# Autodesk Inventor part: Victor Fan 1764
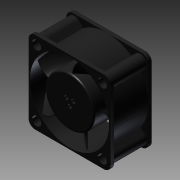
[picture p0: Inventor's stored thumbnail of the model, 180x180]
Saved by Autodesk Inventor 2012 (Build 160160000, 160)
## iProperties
Shininess: 64.0
Length Units: 11272
Angle Units: 11279
Time Units: 11290
Mass Units: 11286
Length Display Precision: 3
Angle Display Precision: 2
Compacted: True
Part Number: Victor Fan 1764
Document SubType Name: Modeling
Created: 2005-12
Designer: Owner
Material: ABS Plastic
Density: 1 g/cm^3
Density: 0.0
Volumn: 0.0
Area: 0.0
PropertySet Name: Model Information
Control State: 0
Master: False
Checked Out: False
Author: Owner
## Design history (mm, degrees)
sketch "Sketch1"
  geometry: L1 (-19.939, 19.939)-(19.939, 19.939); L2 (19.939, 19.939)-(19.939, -19.939); L3 (19.939, -19.939)-(-19.939, -19.939); L4 (-19.939, -19.939)-(-19.939, 19.939); L5 (0, 0)-(0, 19.939); L6 (0, 0)-(0, -19.939); L7 (0, 0)-(19.939, 0); L8 (0, 0)-(-19.939, 0)
  constraints: 16 end point, 4 midpoint, 3 equal length, 3 perpendicular, 2 parallel, 1 horizontal, 1 other
  dimensions: "d0" = 39.878 distance of L1.start L1.end
extrude "Extrusion1" new body sketch "Sketch1" stored distance "d1" = 20.066; taper "d2" = 0 deg
sketch "Sketch2"
  geometry: L1 (19.939, 10.033)-(-19.939, 10.033) reference; L2 (19.939, 10.033)-(19.939, -10.033) reference; L3 (-19.939, -10.033)-(19.939, -10.033) reference; L4 (19.939, 8.331)-(32.639, 8.331); L5 (32.639, 8.331)-(32.639, -8.331); L6 (32.639, -8.331)-(19.939, -8.331); L7 (0, -11.887)-(0, 15.85) reference
  constraints: 6 end point, 2 perpendicular, 2 point on line, 1 parallel
  dimensions: "d3" = 1.7018 distance between parallel lines of L4 L1; "d4" = 12.7 distance of L4.start L4.end; "d5" = 1.7018 distance between parallel lines of L6 L3
revolve "Revolution1" sketch "Sketch2" stored, may be unused: angle "d6" = 90 deg
sketch "Sketch6"
  geometry: L1 (-19.939, 19.939)-(19.939, 19.939) reference; L2 (-19.939, -19.939)-(-19.939, 19.939) reference; L3 (19.939, -19.939)-(-19.939, -19.939) reference; L4 (19.939, 19.939)-(19.939, -19.939) reference; L5 (16.002, 16.002)-(16.002, 19.939); L6 (16.002, 16.002)-(19.939, 16.002); L7 (-16.002, -16.002)-(-19.939, -16.002); L8 (-16.002, -16.002)-(-16.002, -19.939); 2 further points
  constraints: 8 end point, 4 point on line, 3 parallel, 3 perpendicular, 2 horizontal alignment, 2 vertical alignment
  dimensions: "d28" = 32.004 distance of L7.start point (-16.002, 16.002); "d29" = 32.004 distance of L5.start point (-16.002, 16.002)
hole "Hole3" sketch "Sketch6" at (-16.002, 16.002), (16.002, 16.002), (16.002, -16.002), (-16.002, -16.002) diameter "d30" = 4.318; stored, may be unused: countersink angle "d34" = 82 deg, drill point angle "d36" = 118 deg; dims "d31" = 12.7, "d32" = 9.525, "d33" = 6.35, "d35" = 19.05
sketch "Sketch7"
  geometry: L1 (13.721, -1.729)-(11.713, -3.803); L2 (18.283, -6.145)-(16.193, -8.305); C1 r 2.159 at (16.002, -3.937) reference; A1 r 19.939 centre (0, -19.939) between (19.939, -19.939) and (0, 0) reference; A2 r 3.175 centre (16.002, -3.937) between (18.283, -6.145) and (13.721, -1.729)
  constraints: 4 end point, 4 point on circle, 2 tangent, 1 centre point, 1 coincident, 1 parallel
extrude "Extrusion3" join sketch "Sketch7" stored distance "d38" = 19.812; taper "d39" = 0 deg
pattern_circular "Circular Pattern2" dims angle "d42" = 360 deg
fillet "Fillet2" dims "d43" = 3.175
sketch "Sketch8"
  geometry: 1 further point
hole "Hole4" sketch "Sketch8" at (0, 0) diameter "d44" = 38.481; stored, may be unused: countersink angle "d48" = 82 deg, drill point angle "d50" = 118 deg; dims "d45" = 12.7, "d46" = 9.525, "d47" = 6.35, "d49" = 19.05
sketch "Sketch9"
  geometry: L1 (19.939, 16.764)-(19.939, -16.764) reference; L2 (-19.939, -16.764)-(-19.939, 16.764) reference; L3 (10.232, 16.294)-(-3.936, 11.405); L4 (-7.543, -9.416)-(-19.24, -0.045); L5 (-11.131, -4.654)-(-19.158, 1.776); L6 (11.728, 15.253)-(2.006, 11.897); L7 (7.493, -9.456)-(7.493, -17.722); L8 (13.487, -7.924)-(13.487, -13.722); L9 (13.487, -7.924)-(10.847, -5.283); C1 r 2.159 at (16.002, 16.002) reference; A1 r 19.241 centre (0, 0) between (-19.24, -0.045) and (-19.158, 1.776) reference; A2 r 12.065 centre (0, 0) between (-3.936, 11.405) and (-11.131, -4.654); A3 r 12.065 centre (0, 0) between (-7.543, -9.416) and (7.493, -9.456); A4 r 12.065 centre (0, 0) between (10.847, -5.283) and (2.006, 11.897)
  constraints: 14 end point, 12 point on circle, 3 centre point, 3 tangent, 2 parallel, 1 coincident
  dimensions: "d53" = 1.4732 distance between parallel lines of L5 L4; "d54" = 12.446 distance between parallel lines of L1 L7; "d55" = 5.9944 distance between parallel lines of L8 L7; "d58" = 12.065 radius of A2; "d59" = 1.4732 distance between parallel lines of L6 L3; "d60" = 135 deg angle of L8 L9; "d61" = 12.065 radius of A4; "d62" = 12.065 radius of A3
extrude "Extrusion4" join sketch "Sketch9" distance "d63" = 3.81; taper "d64" = 0 deg
sketch "Sketch10"
  geometry: L1 (7.493, -9.456)-(7.493, -17.722) reference; L2 (13.487, -13.722)-(13.487, -7.924) reference; L3 (13.487, -7.924)-(10.847, -5.283) reference; L4 (16.764, -19.939)-(-16.764, -19.939) reference; L5 (-19.939, -16.764)-(-19.939, 16.764) reference; L6 (8.509, -8.553)-(8.509, -18.923); L7 (8.509, -18.923)-(12.471, -18.923); L8 (12.471, -18.923)-(12.471, -8.345); L9 (12.471, -8.345)-(10.341, -6.215); A1 r 19.241 centre (0, 0) between (13.487, -13.722) and (11.728, 15.253) reference; A2 r 12.065 centre (0, 0) between (7.493, -9.456) and (8.509, -8.553)
  constraints: 8 end point, 3 parallel, 3 point on circle, 1 centre point, 1 coincident, 1 perpendicular
  dimensions: "d65" = 1.016 distance between parallel lines of L6 L1; "d66" = 1.016 distance between parallel lines of L4 L7; "d67" = 1.016 distance between parallel lines of L8 L2; "d68" = 1.016 distance between parallel lines of L3 L9
extrude "Extrusion5" cut sketch "Sketch10" distance "d69" = 2.032; taper "d70" = 0 deg
sketch "Sketch11"
  geometry: L1 (16.764, -1.702)-(33.528, -1.702) reference; L2 (33.528, 0)-(0, 0) reference; L3 (26.708, -1.702)-(27.8, -1.702); L4 (27.8, -1.702)-(27.8, 0); L5 (27.8, 0)-(26.708, 0); L6 (26.708, 0)-(26.708, -1.702); L7 (25.273, 0)-(25.273, -1.702) reference; L8 (29.235, 0)-(29.235, -1.702) reference; L9 (26.708, 0)-(25.273, 0); L10 (27.8, 0)-(29.235, 0)
  constraints: 12 end point, 3 collinear, 2 parallel, 2 point on line, 1 horizontal, 1 perpendicular
  dimensions: "d71" = 1.0922 distance between parallel lines of L4 L6
extrude "Extrusion6" cut sketch "Sketch11" distance "d72" = 2.54; taper "d73" = 0 deg
sketch "Sketch12"
  geometry: C1 r 11.938 at (0, 0); A1 r 19.241 centre (0, 0) between (19.24, -0.045) and (19.158, 1.776) reference
  constraints: 1 centre point, 1 coincident, 1 concentric
  dimensions: "d74" = 23.876 diameter of C1
extrude "Extrusion7" join sketch "Sketch12" distance "d75" = 16.256; taper "d76" = 0 deg
fillet "Fillet3" dims "d77" = 0.7874
workplane "Work Plane1"
sketch "Sketch13"
  geometry: L1 (0, 0)-(4, 18.82); L2 (0, 0)-(0, 19.241); L3 (0, 0)-(1.342, 19.194); A1 r 18.669 centre (0, 0) between (3.882, 18.261) and (3.572, 18.324); A2 r 9.196 centre (9.971, 11.37) between (3.882, 18.261) and (0.778, 11.123); A3 r 9.45 centre (9.971, 11.37) between (3.572, 18.324) and (0.523, 11.138); A4 r 11.151 centre (0, 0) between (0.778, 11.123) and (0.523, 11.138); 2 further points
  constraints: 8 point on circle, 6 end point, 4 centre point, 2 coincident, 2 point on line, 1 vertical
  dimensions: "d83" = 4 deg angle of L3 L2; "d84" = 12 deg angle of L1 L2; "d85" = 37.338 diameter of A1; "d86" = 0.254 radial gap between concentric circles of A3 A2
coil "Coil2" sketch "Sketch13" pitch "d99" = 25.4; turns "d101" = 0.15; dims "d100" = 13.97, "d102" = 0, angle "d103" = 90 deg, angle "d104" = 90 deg, "d105" = 0, "d106" = 0
pattern_circular "Circular Pattern4" dims angle "d109" = 360 deg
sketch "Sketch15" dims "d111" = 1.905
  geometry: L1 (0, 0)-(-0.847, 0); L2 (-1.474, 1.076)-(-2.299, 1.552); C1 r 11.151 at (0, 0) reference; C2 r 0.953 at (0.164, -1.762); C3 r 0.953 at (1.803, 1.076)
  constraints: 4 end point, 2 centre point, 1 horizontal, 3 other
  dimensions: "d110" = 1.905 diameter of C3; "d112" = 1.905 diameter of C2; "d114" = 30 deg angle of L1 L2; "d115" = 3.2766 distance of L2.start C2.centre; "d116" = 0 vertical distance of C3.centre L2.start; "d117" = 3.2766 distance of L2.start C3.centre; "d118" = 3.2766 distance of C3.centre C2.centre
extrude "Extrusion8" cut sketch "Sketch15" distance "d119" = 1.905; taper "d120" = 0 deg
body "Solid1"
other parameters: "d37" = 6.35, "d51" = 24.13, "d52" = 1.4732, "d57" = 12.065, "d98" = -0.762
